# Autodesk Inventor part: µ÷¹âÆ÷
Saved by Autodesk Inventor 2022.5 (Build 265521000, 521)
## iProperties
Created: 2025-02
Part Number: µ÷¹âÆ÷
Material: Generic
Document SubType Name: Modeling
Designer: AdminForWorker
Density: 1 g/cm^3
Appearance: Default
Title: µ÷¹âÆ÷
Author: AdminForWorker
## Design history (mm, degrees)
feature "Body1"
body "Solid1"
